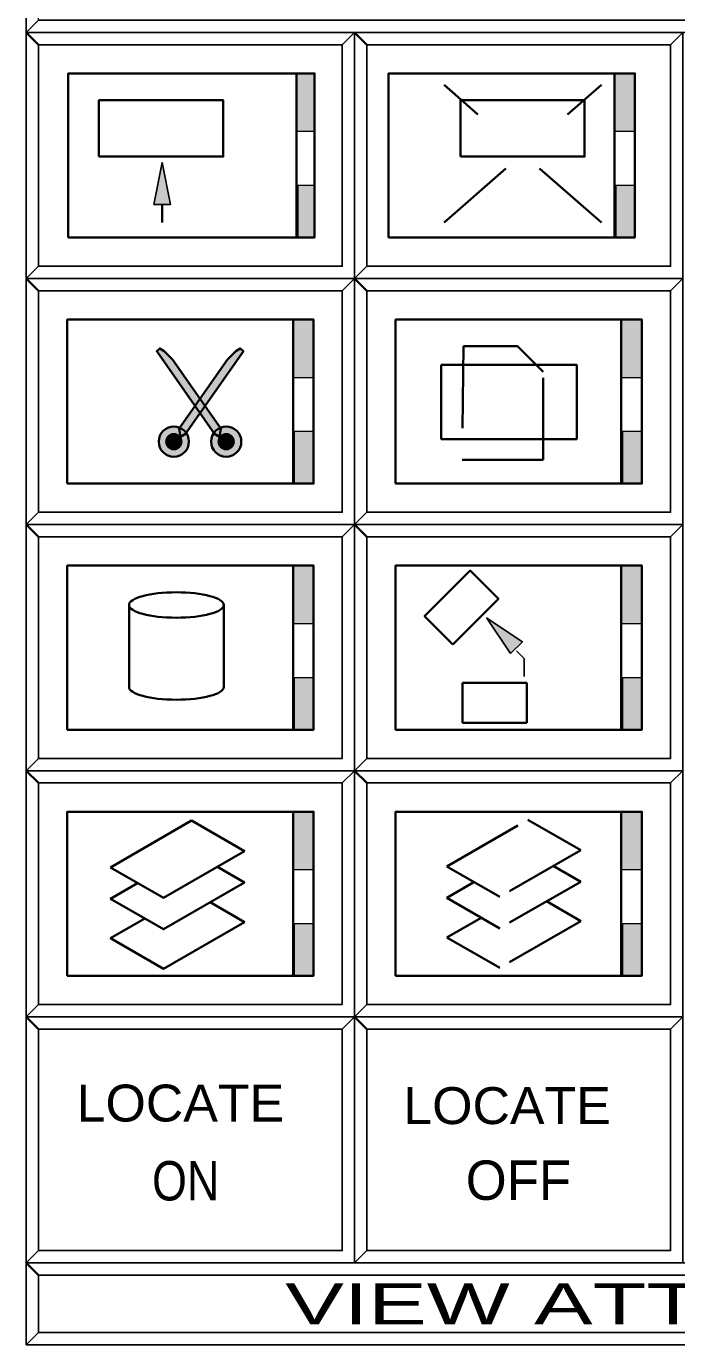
# Model space of a CAD drawing. Extents: x 95906.9 to 95918.9, y 90964.8 to 90972.9.
# Drawn here: x 95916.332 to 95917.125, y 90966.369 to 90967.969 of the extents above; entities that cross this region are included whole.
import ezdxf
from ezdxf.enums import TextEntityAlignment as Align

# ---------------------------------------------------------------- set-up
doc = ezdxf.new("R2010")
doc.units = 0
doc.header["$LTSCALE"] = 0.019
doc.linetypes.add('MEDIUM_DASHED', pattern=[4.5, 3, -1.5])
for name, color, linetype, lineweight in [('1', 7, 'Continuous', 25), ('11', 7, 'Continuous', 25), ('12', 7, 'Continuous', 25), ('2', 7, 'Continuous', 13), ('21', 7, 'Continuous', 25), ('3', 7, 'Continuous', 25), ('4', 7, 'Continuous', 35), ('6', 7, 'Continuous', 35)]:
    doc.layers.add(name, color=color, linetype=linetype, lineweight=lineweight)

msp = doc.modelspace()

# ---------------------------------------------------------------- hatches: boundary and pattern name
at = {"layer": '6'}
for points in [[(95916.6835, 90967.9117), (95916.6608, 90967.9117), (95916.6608, 90967.8412), (95916.6835, 90967.8412)], [(95917.0738, 90967.9117), (95917.048, 90967.9117), (95917.048, 90967.8412), (95917.0738, 90967.8412)], [(95916.4876, 90967.7519), (95916.4978, 90967.8031), (95916.508, 90967.7519)], [(95916.6632, 90967.7117), (95916.6835, 90967.7117), (95916.6835, 90967.775), (95916.6632, 90967.775)], [(95917.0504, 90967.7117), (95917.0738, 90967.7117), (95917.0738, 90967.775), (95917.0504, 90967.775)], [(95916.6823, 90967.6117), (95916.6565, 90967.6117), (95916.6565, 90967.5412), (95916.6823, 90967.5412)], [(95917.0823, 90967.6117), (95917.0565, 90967.6117), (95917.0565, 90967.5412), (95917.0823, 90967.5412)], [(95916.5617, 90967.4723), (95916.4912, 90967.573), (95916.4949, 90967.5765), (95916.5003, 90967.5732), (95916.5105, 90967.563), (95916.5694, 90967.4788), (95916.5677, 90967.4688)], [(95916.5263, 90967.4723), (95916.5968, 90967.573), (95916.5931, 90967.5765), (95916.5877, 90967.5732), (95916.5775, 90967.563), (95916.5186, 90967.4788), (95916.5203, 90967.4688)], [(95916.5305, 90967.4628, 1), (95916.4937, 90967.4628, 1)], [(95916.5213, 90967.4628, 1), (95916.5029, 90967.4628, 1)], [(95916.5575, 90967.4628, 1), (95916.5943, 90967.4628, 1)], [(95916.5667, 90967.4628, 1), (95916.5851, 90967.4628, 1)], [(95916.6589, 90967.4117), (95916.6823, 90967.4117), (95916.6823, 90967.475), (95916.6589, 90967.475)], [(95917.0589, 90967.4117), (95917.0823, 90967.4117), (95917.0823, 90967.475), (95917.0589, 90967.475)], [(95916.6823, 90967.3117), (95916.6565, 90967.3117), (95916.6565, 90967.2412), (95916.6823, 90967.2412)], [(95917.0823, 90967.3117), (95917.0565, 90967.3117), (95917.0565, 90967.2412), (95917.0823, 90967.2412)], [(95916.9224, 90967.2044), (95916.8934, 90967.2478), (95916.9368, 90967.2188)], [(95916.6589, 90967.1117), (95916.6823, 90967.1117), (95916.6823, 90967.175), (95916.6589, 90967.175)], [(95917.0589, 90967.1117), (95917.0823, 90967.1117), (95917.0823, 90967.175), (95917.0589, 90967.175)], [(95916.6823, 90967.0117), (95916.6565, 90967.0117), (95916.6565, 90966.9412), (95916.6823, 90966.9412)], [(95917.0823, 90967.0117), (95917.0565, 90967.0117), (95917.0565, 90966.9412), (95917.0823, 90966.9412)], [(95916.6589, 90966.8117), (95916.6823, 90966.8117), (95916.6823, 90966.875), (95916.6589, 90966.875)], [(95917.0589, 90966.8117), (95917.0823, 90966.8117), (95917.0823, 90966.875), (95917.0589, 90966.875)]]:
    msp.add_hatch(color=256, dxfattribs=at).paths.add_polyline_path(points)

# ---------------------------------------------------------------- linework, layer by layer
at = {"layer": '1'}
for points in [[(95916.3323, 90967.9617), (95917.9323, 90967.9617), (95917.9323, 90968.0617), (95916.3323, 90968.0617)], [(95916.3323, 90967.6617), (95916.7323, 90967.6617), (95916.7323, 90967.9617), (95916.3323, 90967.9617)], [(95916.7323, 90967.6617), (95917.1323, 90967.6617), (95917.1323, 90967.9617), (95916.7323, 90967.9617)], [(95916.3323, 90967.3617), (95916.7323, 90967.3617), (95916.7323, 90967.6617), (95916.3323, 90967.6617)], [(95916.7323, 90967.3617), (95917.1323, 90967.3617), (95917.1323, 90967.6617), (95916.7323, 90967.6617)], [(95916.3323, 90967.0617), (95916.7323, 90967.0617), (95916.7323, 90967.3617), (95916.3323, 90967.3617)], [(95916.7323, 90967.0617), (95917.1323, 90967.0617), (95917.1323, 90967.3617), (95916.7323, 90967.3617)], [(95916.3323, 90966.7617), (95916.7323, 90966.7617), (95916.7323, 90967.0617), (95916.3323, 90967.0617)], [(95916.7323, 90966.7617), (95917.1323, 90966.7617), (95917.1323, 90967.0617), (95916.7323, 90967.0617)], [(95916.3323, 90966.4617), (95916.7323, 90966.4617), (95916.7323, 90966.7617), (95916.3323, 90966.7617)], [(95916.7323, 90966.4617), (95917.1323, 90966.4617), (95917.1323, 90966.7617), (95916.7323, 90966.7617)], [(95916.3323, 90966.3617), (95917.9323, 90966.3617), (95917.9323, 90966.4617), (95916.3323, 90966.4617)]]:
    msp.add_lwpolyline(points, close=True, dxfattribs=at)
at = {"layer": '11'}
for points in [[(95916.3473, 90967.6767), (95916.7173, 90967.6767), (95916.7173, 90967.9467), (95916.3473, 90967.9467)], [(95916.7473, 90967.6767), (95917.1173, 90967.6767), (95917.1173, 90967.9467), (95916.7473, 90967.9467)], [(95916.3473, 90967.3767), (95916.7173, 90967.3767), (95916.7173, 90967.6467), (95916.3473, 90967.6467)], [(95916.7473, 90967.3767), (95917.1173, 90967.3767), (95917.1173, 90967.6467), (95916.7473, 90967.6467)], [(95916.3473, 90967.0767), (95916.7173, 90967.0767), (95916.7173, 90967.3467), (95916.3473, 90967.3467)], [(95916.7473, 90967.0767), (95917.1173, 90967.0767), (95917.1173, 90967.3467), (95916.7473, 90967.3467)], [(95916.3473, 90966.7767), (95916.7173, 90966.7767), (95916.7173, 90967.0467), (95916.3473, 90967.0467)], [(95916.7473, 90966.7767), (95917.1173, 90966.7767), (95917.1173, 90967.0467), (95916.7473, 90967.0467)], [(95916.3473, 90966.4767), (95916.7173, 90966.4767), (95916.7173, 90966.7467), (95916.3473, 90966.7467)], [(95916.7473, 90966.4767), (95917.1173, 90966.4767), (95917.1173, 90966.7467), (95916.7473, 90966.7467)]]:
    msp.add_lwpolyline(points, close=True, dxfattribs=at)
at = {"layer": '12'}
msp.add_lwpolyline([(95916.3473, 90967.6767), (95916.7173, 90967.6767), (95916.7173, 90967.9467), (95916.3473, 90967.9467)], close=True, dxfattribs=at)
at = {"layer": '2'}
for points in [[(95916.3323, 90968.0617), (95916.3323, 90967.9617), (95916.3473, 90967.9767), (95916.3473, 90968.0467), (95917.9173, 90968.0467), (95917.9323, 90968.0617)], [(95916.3323, 90967.9617), (95916.3323, 90967.6617), (95916.3473, 90967.6767), (95916.3473, 90967.9467), (95916.7173, 90967.9467), (95916.7323, 90967.9617)], [(95916.7323, 90967.9617), (95916.7323, 90967.6617), (95916.7473, 90967.6767), (95916.7473, 90967.9467), (95917.1173, 90967.9467), (95917.1323, 90967.9617)], [(95916.3323, 90967.6617), (95916.3323, 90967.3617), (95916.3473, 90967.3767), (95916.3473, 90967.6467), (95916.7173, 90967.6467), (95916.7323, 90967.6617)], [(95916.7323, 90967.6617), (95916.7323, 90967.3617), (95916.7473, 90967.3767), (95916.7473, 90967.6467), (95917.1173, 90967.6467), (95917.1323, 90967.6617)], [(95916.3323, 90967.3617), (95916.3323, 90967.0617), (95916.3473, 90967.0767), (95916.3473, 90967.3467), (95916.7173, 90967.3467), (95916.7323, 90967.3617)], [(95916.7323, 90967.3617), (95916.7323, 90967.0617), (95916.7473, 90967.0767), (95916.7473, 90967.3467), (95917.1173, 90967.3467), (95917.1323, 90967.3617)], [(95916.3323, 90967.0617), (95916.3323, 90966.7617), (95916.3473, 90966.7767), (95916.3473, 90967.0467), (95916.7173, 90967.0467), (95916.7323, 90967.0617)], [(95916.7323, 90967.0617), (95916.7323, 90966.7617), (95916.7473, 90966.7767), (95916.7473, 90967.0467), (95917.1173, 90967.0467), (95917.1323, 90967.0617)], [(95916.3323, 90966.7617), (95916.3323, 90966.4617), (95916.3473, 90966.4767), (95916.3473, 90966.7467), (95916.7173, 90966.7467), (95916.7323, 90966.7617)], [(95916.7323, 90966.7617), (95916.7323, 90966.4617), (95916.7473, 90966.4767), (95916.7473, 90966.7467), (95917.1173, 90966.7467), (95917.1323, 90966.7617)], [(95916.3323, 90966.4617), (95916.3323, 90966.3617), (95916.3473, 90966.3767), (95916.3473, 90966.4467), (95917.9173, 90966.4467), (95917.9323, 90966.4617)]]:
    msp.add_lwpolyline(points, close=True, dxfattribs=at)
at = {"layer": '21'}
msp.add_lwpolyline([(95916.3473, 90966.3767), (95917.9173, 90966.3767), (95917.9173, 90966.4467), (95916.3473, 90966.4467)], close=True, dxfattribs=at)
at = {"layer": '3'}
for points in [[(95916.3323, 90967.9617), (95917.9323, 90967.9617), (95917.9323, 90968.0617), (95917.9173, 90968.0467), (95917.9173, 90967.9767), (95916.3473, 90967.9767)], [(95916.3323, 90967.6617), (95916.7323, 90967.6617), (95916.7323, 90967.9617), (95916.7173, 90967.9467), (95916.7173, 90967.6767), (95916.3473, 90967.6767)], [(95916.7323, 90967.6617), (95917.1323, 90967.6617), (95917.1323, 90967.9617), (95917.1173, 90967.9467), (95917.1173, 90967.6767), (95916.7473, 90967.6767)], [(95916.3323, 90967.3617), (95916.7323, 90967.3617), (95916.7323, 90967.6617), (95916.7173, 90967.6467), (95916.7173, 90967.3767), (95916.3473, 90967.3767)], [(95916.7323, 90967.3617), (95917.1323, 90967.3617), (95917.1323, 90967.6617), (95917.1173, 90967.6467), (95917.1173, 90967.3767), (95916.7473, 90967.3767)], [(95916.3323, 90967.0617), (95916.7323, 90967.0617), (95916.7323, 90967.3617), (95916.7173, 90967.3467), (95916.7173, 90967.0767), (95916.3473, 90967.0767)], [(95916.7323, 90967.0617), (95917.1323, 90967.0617), (95917.1323, 90967.3617), (95917.1173, 90967.3467), (95917.1173, 90967.0767), (95916.7473, 90967.0767)], [(95916.3323, 90966.7617), (95916.7323, 90966.7617), (95916.7323, 90967.0617), (95916.7173, 90967.0467), (95916.7173, 90966.7767), (95916.3473, 90966.7767)], [(95916.7323, 90966.7617), (95917.1323, 90966.7617), (95917.1323, 90967.0617), (95917.1173, 90967.0467), (95917.1173, 90966.7767), (95916.7473, 90966.7767)], [(95916.3323, 90966.4617), (95916.7323, 90966.4617), (95916.7323, 90966.7617), (95916.7173, 90966.7467), (95916.7173, 90966.4767), (95916.3473, 90966.4767)], [(95916.7323, 90966.4617), (95917.1323, 90966.4617), (95917.1323, 90966.7617), (95917.1173, 90966.7467), (95917.1173, 90966.4767), (95916.7473, 90966.4767)], [(95916.3323, 90966.3617), (95917.9323, 90966.3617), (95917.9323, 90966.4617), (95917.9173, 90966.4467), (95917.9173, 90966.3767), (95916.3473, 90966.3767)]]:
    msp.add_lwpolyline(points, close=True, dxfattribs=at)
at = {"layer": '4'}
for p, q in [((95916.3473, 90967.9467), (95916.3323, 90967.9617)), ((95916.7473, 90967.9467), (95916.7323, 90967.9617)), ((95916.3473, 90967.6467), (95916.3323, 90967.6617)), ((95916.7473, 90967.6467), (95916.7323, 90967.6617)), ((95916.3473, 90967.3467), (95916.3323, 90967.3617)), ((95916.7473, 90967.3467), (95916.7323, 90967.3617)), ((95916.3473, 90967.0467), (95916.3323, 90967.0617)), ((95916.7473, 90967.0467), (95916.7323, 90967.0617)), ((95916.3473, 90966.7467), (95916.3323, 90966.7617)), ((95916.7473, 90966.7467), (95916.7323, 90966.7617)), ((95916.3473, 90966.4467), (95916.3323, 90966.4617))]:
    msp.add_line(p, q, dxfattribs=at)
at = {"layer": '6', "linetype": 'MEDIUM_DASHED'}
for p, q in [((95916.8414, 90967.73), (95917.033, 90967.8979)), ((95917.033, 90967.73), (95916.8414, 90967.8979))]:
    msp.add_line(p, q, dxfattribs=at)
at = {"layer": '6'}
for p, q in [((95916.4978, 90967.73), (95916.4978, 90967.7519)), ((95916.4575, 90967.2637), (95916.4575, 90967.1637)), ((95916.5729, 90967.2637), (95916.5729, 90967.1637))]:
    msp.add_line(p, q, dxfattribs=at)
for points in [[(95916.3835, 90967.7117), (95916.6835, 90967.7117), (95916.6835, 90967.9117), (95916.3835, 90967.9117)], [(95916.6835, 90967.7117), (95916.6616, 90967.7117), (95916.6616, 90967.9117), (95916.6835, 90967.9117)], [(95916.7738, 90967.7117), (95917.0738, 90967.7117), (95917.0738, 90967.9117), (95916.7738, 90967.9117)], [(95917.0738, 90967.7117), (95917.0488, 90967.7117), (95917.0488, 90967.9117), (95917.0738, 90967.9117)], [(95916.4209, 90967.8104), (95916.5723, 90967.8104), (95916.5723, 90967.879), (95916.4209, 90967.879)], [(95916.8612, 90967.8104), (95917.0126, 90967.8104), (95917.0126, 90967.879), (95916.8612, 90967.879)], [(95916.3823, 90967.4117), (95916.6823, 90967.4117), (95916.6823, 90967.6117), (95916.3823, 90967.6117)], [(95916.6823, 90967.4117), (95916.6573, 90967.4117), (95916.6573, 90967.6117), (95916.6823, 90967.6117)], [(95916.7823, 90967.4117), (95917.0823, 90967.4117), (95917.0823, 90967.6117), (95916.7823, 90967.6117)], [(95917.0823, 90967.4117), (95917.0573, 90967.4117), (95917.0573, 90967.6117), (95917.0823, 90967.6117)], [(95916.5617, 90967.4723), (95916.4912, 90967.573), (95916.4949, 90967.5765), (95916.5003, 90967.5732), (95916.5105, 90967.563), (95916.5694, 90967.4788), (95916.5677, 90967.4688)], [(95916.5263, 90967.4723), (95916.5968, 90967.573), (95916.5931, 90967.5765), (95916.5877, 90967.5732), (95916.5775, 90967.563), (95916.5186, 90967.4788), (95916.5203, 90967.4688)], [(95916.8379, 90967.5563), (95917.003, 90967.5563), (95917.003, 90967.466), (95916.8379, 90967.466)], [(95916.3823, 90967.1117), (95916.6823, 90967.1117), (95916.6823, 90967.3117), (95916.3823, 90967.3117)], [(95916.6823, 90967.1117), (95916.6573, 90967.1117), (95916.6573, 90967.3117), (95916.6823, 90967.3117)], [(95916.7823, 90967.1117), (95917.0823, 90967.1117), (95917.0823, 90967.3117), (95916.7823, 90967.3117)], [(95916.8521, 90967.2157), (95916.9076, 90967.2712), (95916.8731, 90967.3057), (95916.8176, 90967.2502)], [(95917.0823, 90967.1117), (95917.0573, 90967.1117), (95917.0573, 90967.3117), (95917.0823, 90967.3117)], [(95916.3823, 90966.8117), (95916.6823, 90966.8117), (95916.6823, 90967.0117), (95916.3823, 90967.0117)], [(95916.6823, 90966.8117), (95916.6573, 90966.8117), (95916.6573, 90967.0117), (95916.6823, 90967.0117)], [(95916.7823, 90966.8117), (95917.0823, 90966.8117), (95917.0823, 90967.0117), (95916.7823, 90967.0117)], [(95917.0823, 90966.8117), (95917.0573, 90966.8117), (95917.0573, 90967.0117), (95917.0823, 90967.0117)], [(95916.435, 90966.9438), (95916.5336, 90967.0008), (95916.5981, 90966.9636), (95916.4994, 90966.9067)]]:
    msp.add_lwpolyline(points, close=True, dxfattribs=at)
at = {"layer": '6', "lineweight": 13}
for points in [[(95916.6835, 90967.9117), (95916.6608, 90967.9117), (95916.6608, 90967.8412), (95916.6835, 90967.8412)], [(95917.0738, 90967.9117), (95917.048, 90967.9117), (95917.048, 90967.8412), (95917.0738, 90967.8412)], [(95916.6632, 90967.7117), (95916.6835, 90967.7117), (95916.6835, 90967.775), (95916.6632, 90967.775)], [(95917.0504, 90967.7117), (95917.0738, 90967.7117), (95917.0738, 90967.775), (95917.0504, 90967.775)], [(95916.6823, 90967.6117), (95916.6565, 90967.6117), (95916.6565, 90967.5412), (95916.6823, 90967.5412)], [(95917.0823, 90967.6117), (95917.0565, 90967.6117), (95917.0565, 90967.5412), (95917.0823, 90967.5412)], [(95916.6589, 90967.4117), (95916.6823, 90967.4117), (95916.6823, 90967.475), (95916.6589, 90967.475)], [(95917.0589, 90967.4117), (95917.0823, 90967.4117), (95917.0823, 90967.475), (95917.0589, 90967.475)], [(95916.6823, 90967.3117), (95916.6565, 90967.3117), (95916.6565, 90967.2412), (95916.6823, 90967.2412)], [(95917.0823, 90967.3117), (95917.0565, 90967.3117), (95917.0565, 90967.2412), (95917.0823, 90967.2412)], [(95916.6589, 90967.1117), (95916.6823, 90967.1117), (95916.6823, 90967.175), (95916.6589, 90967.175)], [(95917.0589, 90967.1117), (95917.0823, 90967.1117), (95917.0823, 90967.175), (95917.0589, 90967.175)], [(95916.6823, 90967.0117), (95916.6565, 90967.0117), (95916.6565, 90966.9412), (95916.6823, 90966.9412)], [(95917.0823, 90967.0117), (95917.0565, 90967.0117), (95917.0565, 90966.9412), (95917.0823, 90966.9412)], [(95916.6589, 90966.8117), (95916.6823, 90966.8117), (95916.6823, 90966.875), (95916.6589, 90966.875)], [(95917.0589, 90966.8117), (95917.0823, 90966.8117), (95917.0823, 90966.875), (95917.0589, 90966.875)]]:
    msp.add_lwpolyline(points, close=True, dxfattribs=at)
at = {"layer": '6', "lineweight": 25}
for points in [[(95916.4876, 90967.7519), (95916.4978, 90967.8031), (95916.508, 90967.7519)], [(95916.9224, 90967.2044), (95916.8934, 90967.2478), (95916.9368, 90967.2188)]]:
    msp.add_lwpolyline(points, close=True, dxfattribs=at)
at = {"layer": '6', "linetype": 'MEDIUM_DASHED'}
for points in [[(95916.8634, 90967.4405), (95916.9622, 90967.4405), (95916.9622, 90967.5478), (95916.9307, 90967.5793), (95916.8651, 90967.5793)], [(95916.8636, 90967.1199), (95916.9421, 90967.1199), (95916.9421, 90967.1687), (95916.8636, 90967.1687)], [(95916.8447, 90966.9449), (95916.9433, 90967.0019), (95917.0078, 90966.9647), (95916.9091, 90966.9078)]]:
    msp.add_lwpolyline(points, close=True, dxfattribs=at)
at = {"layer": '6', "lineweight": 25}
msp.add_lwpolyline([(95916.9389, 90967.1767), (95916.9389, 90967.1984), (95916.9294, 90967.2077)], dxfattribs=at)
at = {"layer": '6'}
for points in [[(95916.5645, 90966.9447), (95916.5981, 90966.9253), (95916.4994, 90966.8684), (95916.435, 90966.9056), (95916.468, 90966.9246)], [(95916.5563, 90966.9014), (95916.5981, 90966.8772), (95916.4994, 90966.8202), (95916.435, 90966.8574), (95916.4769, 90966.8814)]]:
    msp.add_lwpolyline(points, dxfattribs=at)
at = {"layer": '6', "linetype": 'MEDIUM_DASHED'}
for points in [[(95916.9742, 90966.9458), (95917.0078, 90966.9264), (95916.9091, 90966.8695), (95916.8447, 90966.9067), (95916.8777, 90966.9257)], [(95916.966, 90966.9025), (95917.0078, 90966.8783), (95916.9091, 90966.8213), (95916.8447, 90966.8585), (95916.8866, 90966.8825)]]:
    msp.add_lwpolyline(points, dxfattribs=at)
at = {"layer": '6'}
for centre, radius in [((95916.5121, 90967.4628), 0.0184), ((95916.5121, 90967.4628), 0.00923), ((95916.5759, 90967.4628), 0.0184), ((95916.5759, 90967.4628), 0.00923)]:
    msp.add_circle(centre, radius, dxfattribs=at)
msp.add_ellipse((95916.5152, 90967.2637), major_axis=(0.0577, 0), ratio=0.26816, dxfattribs=at)
msp.add_ellipse((95916.5152, 90967.1637), major_axis=(0.0577, 0), ratio=0.26816, start_param=3.141891, end_param=6.282846, dxfattribs=at)

# ---------------------------------------------------------------- texts
at = {"layer": '21', "width": 1.6}
msp.add_text('    VIEW ATTRIBUTES    ', height=0.04999, dxfattribs=at).set_placement((95917.1322, 90966.3867), align=Align.CENTER)
at = {"layer": '6'}
for s, height, width, p in [('LOCATE', 0.045, 1.05, (95916.5201, 90966.634)), ('LOCATE', 0.045, 1.05, (95916.9181, 90966.6309)), ('ON', 0.048, 0.85, (95916.5265, 90966.5378))]:
    msp.add_text(s, height=height, dxfattribs=dict(at, width=width)).set_placement(p, align=Align.CENTER)
msp.add_text('OFF', height=0.048, dxfattribs=at).set_placement((95916.9319, 90966.5385), align=Align.CENTER)

doc.saveas('drawing.dxf')
